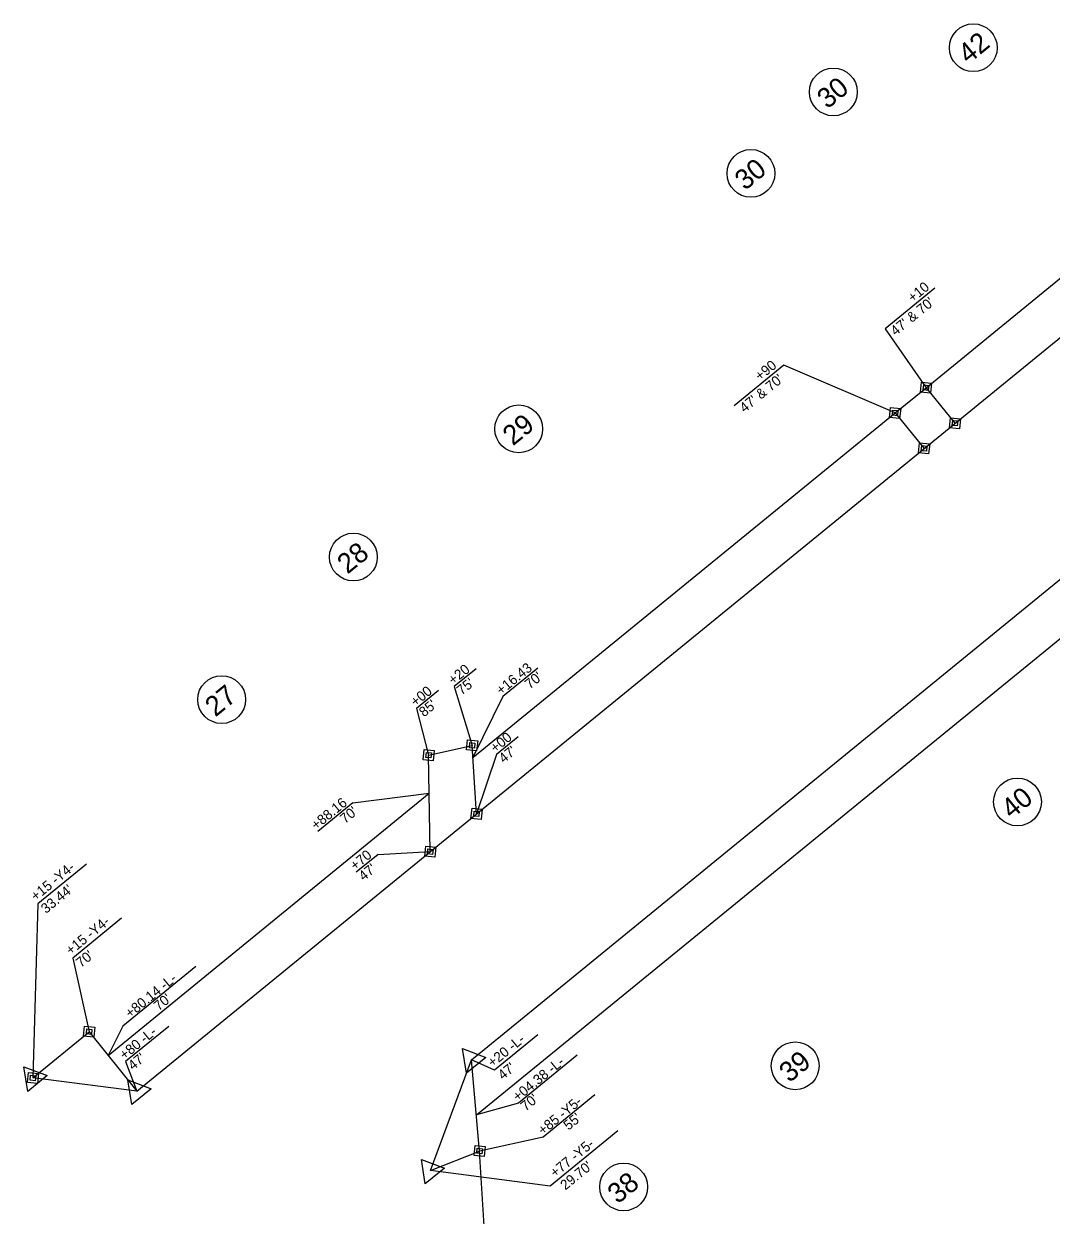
# Model space of a CAD drawing. Extents: x 2320946 to 2332748, y 597838 to 612698.
# Drawn here: x 2322965 to 2323481, y 599108 to 599706 of the extents above; entities that cross this region are included whole.
import ezdxf

# ---------------------------------------------------------------- set-up
doc = ezdxf.new("R2010")
doc.units = 0
for name, color, linetype in [('Prop Easement Construction', 7, 'Continuous'), ('Prop Easement Construction Station Offsets', 7, 'Continuous'), ('Prop Easement Permanent Drainage', 7, 'Continuous'), ('Prop Easement Permanent Drainage Station Offsets', 7, 'Continuous'), ('Prop Easement Permanent Utility', 7, 'Continuous'), ('Prop Easement Permanent Utility Station Offsets', 7, 'Continuous'), ('Prop Parcel Number CELL', 7, 'Continuous'), ('Prop ROW Marker CELL', 7, 'Continuous'), ('Prop ROW Permanent Easement CELL', 7, 'Continuous'), ('Prop ROW RW Lines', 7, 'Continuous'), ('Prop ROW Station Offsets', 7, 'Continuous')]:
    doc.layers.add(name, color=color, linetype=linetype)

msp = doc.modelspace()

# ---------------------------------------------------------------- linework, layer by layer
at = {"layer": 'Prop Easement Construction'}
for p, q in [((2323417.87, 599523.08), (2323545.68, 599627.42)), ((2323190.45, 599337.42), (2323402.37, 599510.43)), ((2323192.2, 599158.11), (2323576.17, 599471.58)), ((2323007.42, 599187.99), (2323168.55, 599319.54)), ((2323196.52, 599097.06), (2323193.8, 599139.98))]:
    msp.add_line(p, q, dxfattribs=at)
at = {"layer": 'Prop Easement Construction Station Offsets'}
for p, q in [((2323222.96, 599382.4), (2323205.43, 599368.09)), ((2323130.23, 599314.81), (2323112.61, 599300.42)), ((2323051.43, 599232.54), (2323014.7, 599202.56)), ((2323242.75, 599188.04), (2323213.38, 599164.06))]:
    msp.add_line(p, q, dxfattribs=at)
for points in [[(2323205.43, 599368.09), (2323190.45, 599337.42)], [(2323130.23, 599314.81), (2323168.55, 599319.54)], [(2323014.7, 599202.56), (2323007.42, 599187.99)], [(2323213.41, 599164.03), (2323192.2, 599158.11)]]:
    msp.add_lwpolyline(points, dxfattribs=at)
at = {"layer": 'Prop Easement Permanent Drainage'}
for p, q in [((2323402.37, 599510.43), (2323417.87, 599523.08)), ((2323417.87, 599523.08), (2323432.41, 599505.26)), ((2323402.37, 599510.43), (2323416.92, 599492.61))]:
    msp.add_line(p, q, dxfattribs=at)
at = {"layer": 'Prop Easement Permanent Drainage Station Offsets'}
for p, q in [((2323422.28, 599573.04), (2323397.29, 599552.64)), ((2323346.51, 599534.47), (2323321.52, 599514.07)), ((2323402.37, 599510.43), (2323346.51, 599534.47))]:
    msp.add_line(p, q, dxfattribs=at)
msp.add_lwpolyline([(2323397.29, 599552.64), (2323417.87, 599523.08)], dxfattribs=at)
at = {"layer": 'Prop Easement Permanent Utility'}
for p, q in [((2323168.24, 599338.65), (2323190.06, 599343.55)), ((2323192.27, 599309.21), (2323190.06, 599343.55)), ((2323169.03, 599290.24), (2323168.24, 599338.65)), ((2322969.61, 599176.64), (2322997.84, 599199.87)), ((2322997.84, 599199.87), (2323021.85, 599170.08)), ((2323193.8, 599139.98), (2323189.75, 599185.81)), ((2323169.13, 599130.2), (2323193.8, 599139.98))]:
    msp.add_line(p, q, dxfattribs=at)
at = {"layer": 'Prop Easement Permanent Utility Station Offsets'}
for p, q in [((2323192.1, 599382), (2323181.13, 599373.04)), ((2323173.17, 599371.05), (2323162.2, 599362.1)), ((2323213.22, 599347.88), (2323202.25, 599338.93)), ((2323142.86, 599288.81), (2323131.89, 599279.85)), ((2323014.08, 599256.83), (2322989.61, 599236.85)), ((2323251.72, 599168.22), (2323225.7, 599146.97))]:
    msp.add_line(p, q, dxfattribs=at)
for points in [[(2323181.13, 599373.04), (2323190.06, 599343.55)], [(2323162.2, 599362.1), (2323168.24, 599338.65)], [(2323202.25, 599338.93), (2323192.27, 599309.21)], [(2323142.86, 599288.81), (2323169.03, 599290.24)], [(2322989.61, 599236.85), (2322997.84, 599199.87)], [(2323225.7, 599146.97), (2323193.8, 599139.98)]]:
    msp.add_lwpolyline(points, dxfattribs=at)
at = {"layer": 'Prop Parcel Number CELL'}
for p, q in [((2323441.61, 599693.73), (2323441.61, 599693.73)), ((2323371.35, 599671.55), (2323371.35, 599671.55)), ((2323330, 599630.66), (2323330, 599630.66)), ((2323213.45, 599502.42), (2323213.45, 599502.42)), ((2323130.47, 599438.09), (2323130.47, 599438.09)), ((2323064.34, 599366.54), (2323064.34, 599366.54)), ((2323463.77, 599315.17), (2323463.77, 599315.17)), ((2323352.22, 599182.76), (2323352.22, 599182.76)), ((2323266.13, 599121.95), (2323266.13, 599121.95))]:
    msp.add_line(p, q, dxfattribs=at)
for centre in [(2323441.61, 599693.73), (2323371.35, 599671.55), (2323330, 599630.66), (2323213.45, 599502.42), (2323130.47, 599438.09), (2323064.34, 599366.54), (2323463.77, 599315.17), (2323352.22, 599182.76), (2323266.13, 599121.95)]:
    msp.add_circle(centre, 12, dxfattribs=at)
at = {"layer": 'Prop ROW Marker CELL'}
for p, q in [((2323417.87, 599523.08), (2323417.87, 599523.08)), ((2323402.37, 599510.43), (2323402.37, 599510.43)), ((2323432.41, 599505.26), (2323432.41, 599505.26)), ((2323416.92, 599492.61), (2323416.92, 599492.61)), ((2323190.06, 599343.55), (2323190.06, 599343.55)), ((2323168.24, 599338.65), (2323168.24, 599338.65)), ((2323192.27, 599309.21), (2323192.27, 599309.21)), ((2323169.03, 599290.24), (2323169.03, 599290.24)), ((2322997.84, 599199.87), (2322997.84, 599199.87)), ((2323189.75, 599185.81), (2323189.75, 599185.81)), ((2322969.61, 599176.64), (2322969.61, 599176.64)), ((2322969.61, 599176.64), (2322969.61, 599176.64)), ((2323021.85, 599170.08), (2323021.85, 599170.08)), ((2323193.8, 599139.98), (2323193.8, 599139.98)), ((2323169.13, 599130.2), (2323169.13, 599130.2))]:
    msp.add_line(p, q, dxfattribs=at)
for points in [[(2323187.18, 599179.06), (2323185.2, 599191.38), (2323196.87, 599186.97)], [(2322967.04, 599169.9), (2322965.05, 599182.22), (2322976.72, 599177.81)], [(2323019.29, 599163.34), (2323017.3, 599175.66), (2323028.97, 599171.25)], [(2323166.56, 599123.46), (2323164.57, 599135.78), (2323176.24, 599131.36)]]:
    msp.add_lwpolyline(points, close=True, dxfattribs=at)
at = {"layer": 'Prop ROW Permanent Easement CELL'}
for points in [[(2323415.59, 599525.87), (2323420.65, 599525.35), (2323420.14, 599520.29), (2323415.08, 599520.8)], [(2323416.73, 599524.47), (2323419.26, 599524.22), (2323419, 599521.68), (2323416.47, 599521.94)], [(2323400.1, 599513.22), (2323405.16, 599512.71), (2323404.65, 599507.64), (2323399.58, 599508.15)], [(2323401.23, 599511.82), (2323403.77, 599511.57), (2323403.51, 599509.04), (2323400.98, 599509.29)], [(2323430.13, 599508.05), (2323435.2, 599507.54), (2323434.69, 599502.47), (2323429.62, 599502.98)], [(2323431.27, 599506.66), (2323433.8, 599506.4), (2323433.55, 599503.87), (2323431.02, 599504.12)], [(2323414.64, 599495.4), (2323419.71, 599494.89), (2323419.19, 599489.82), (2323414.13, 599490.34)], [(2323415.78, 599494.01), (2323418.31, 599493.75), (2323418.06, 599491.22), (2323415.52, 599491.47)], [(2323187.78, 599346.34), (2323192.85, 599345.83), (2323192.33, 599340.76), (2323187.27, 599341.28)], [(2323188.92, 599344.95), (2323191.45, 599344.69), (2323191.2, 599342.16), (2323188.66, 599342.41)], [(2323165.97, 599341.44), (2323171.03, 599340.93), (2323170.52, 599335.86), (2323165.45, 599336.37)], [(2323167.1, 599340.04), (2323169.64, 599339.79), (2323169.38, 599337.26), (2323166.85, 599337.51)], [(2323190, 599312), (2323195.06, 599311.49), (2323194.55, 599306.43), (2323189.49, 599306.94)], [(2323191.14, 599310.61), (2323193.67, 599310.35), (2323193.41, 599307.82), (2323190.88, 599308.08)], [(2323166.76, 599293.03), (2323171.82, 599292.52), (2323171.31, 599287.45), (2323166.25, 599287.97)], [(2323167.9, 599291.64), (2323170.43, 599291.38), (2323170.17, 599288.85), (2323167.64, 599289.1)], [(2322995.56, 599202.65), (2323000.63, 599202.14), (2323000.11, 599197.08), (2322995.05, 599197.59)], [(2322996.7, 599201.26), (2322999.23, 599201), (2322998.98, 599198.47), (2322996.44, 599198.73)], [(2322967.33, 599179.43), (2322972.39, 599178.92), (2322971.88, 599173.85), (2322966.82, 599174.37)], [(2322968.47, 599178.04), (2322971, 599177.78), (2322970.74, 599175.25), (2322968.21, 599175.5)], [(2323191.52, 599142.77), (2323196.59, 599142.26), (2323196.07, 599137.19), (2323191.01, 599137.7)], [(2323192.66, 599141.37), (2323195.19, 599141.12), (2323194.93, 599138.59), (2323192.4, 599138.84)]]:
    msp.add_lwpolyline(points, close=True, dxfattribs=at)
at = {"layer": 'Prop ROW RW Lines'}
for p, q in [((2323021.85, 599170.08), (2323653.18, 599685.5)), ((2323189.75, 599185.81), (2323538.33, 599470.39)), ((2323169.13, 599130.2), (2323189.75, 599185.81)), ((2323021.85, 599170.08), (2322969.61, 599176.64))]:
    msp.add_line(p, q, dxfattribs=at)
at = {"layer": 'Prop ROW Station Offsets'}
for p, q in [((2322996.49, 599283.96), (2322972.01, 599263.98)), ((2322972.01, 599263.98), (2322969.61, 599176.64)), ((2323037.84, 599202.55), (2323016.12, 599184.82)), ((2323223.06, 599198.23), (2323201.34, 599180.51)), ((2323263.19, 599150.08), (2323229.22, 599122.35)), ((2323229.22, 599122.35), (2323169.13, 599130.2))]:
    msp.add_line(p, q, dxfattribs=at)
for points in [[(2323016.12, 599184.82), (2323021.85, 599170.08)], [(2323201.34, 599180.51), (2323189.75, 599185.81)]]:
    msp.add_lwpolyline(points, dxfattribs=at)

# ---------------------------------------------------------------- texts
at = {"layer": 'Prop Easement Construction Station Offsets'}
for s, p in [('+16.43', (2323204.65, 599368.58)), ("70'", (2323219.02, 599371.59)), ('+88.16', (2323111.78, 599300.87)), ("70'", (2323126.29, 599304.01)), ('+80.14 -L-', (2323018.45, 599206.43)), ("70'", (2323032.79, 599210.07)), ('+04.38 -L-', (2323212.98, 599164.55)), ("70'", (2323216.94, 599159.71))]:
    msp.add_text(s, height=5, rotation=39.22799, dxfattribs=at).set_placement(p)
at = {"layer": 'Prop Easement Permanent Drainage Station Offsets'}
for s, p in [('+10', (2323411.22, 599565.63)), ("47' & 70'", (2323402.58, 599548.89)), ('+90', (2323334.53, 599526.3)), ("47' & 70'", (2323326.81, 599510.32))]:
    msp.add_text(s, height=5, rotation=39.22799, dxfattribs=at).set_placement(p)
at = {"layer": 'Prop Easement Permanent Utility Station Offsets'}
for s, p in [('+20', (2323180.58, 599373.72)), ('+00', (2323161.65, 599362.77)), ("75'", (2323184.85, 599368.49)), ("85'", (2323165.92, 599357.55)), ('+00', (2323201.69, 599339.61)), ("47'", (2323205.96, 599334.38)), ('+70', (2323131.34, 599280.53)), ("47'", (2323135.61, 599275.3)), ('+15 -Y4-', (2322988.62, 599238.06)), ("70'", (2322993.76, 599231.77)), ('+85 -Y5-', (2323225.61, 599147.71)), ("55'", (2323238.44, 599150.11))]:
    msp.add_text(s, height=5, rotation=39.22799, dxfattribs=at).set_placement(p)
at = {"layer": 'Prop Parcel Number CELL'}
for s, p in [('42', (2323439.14, 599685.25)), ('30', (2323368.38, 599662.67)), ('30', (2323327.04, 599621.79)), ('29', (2323210.55, 599493.6)), ('28', (2323127.51, 599429.22)), ('27', (2323061.2, 599357.53)), ('40', (2323460.8, 599306.29)), ('39', (2323349.32, 599173.94)), ('38', (2323263.17, 599113.08))]:
    msp.add_text(s, height=10, rotation=39.22799, dxfattribs=at).set_placement(p)
at = {"layer": 'Prop ROW Station Offsets'}
for s, p in [('+15 -Y4-', (2322971.03, 599265.19)), ("33.44'", (2322976.17, 599258.9)), ('+80 -L-', (2323015.57, 599185.5)), ('+20 -L-', (2323200.36, 599181.72)), ("47'", (2323019.84, 599180.27)), ("47'", (2323205.49, 599175.42)), ('+77 -Y5-', (2323231.72, 599126.41)), ("29.70'", (2323236.86, 599120.11))]:
    msp.add_text(s, height=5, rotation=39.22799, dxfattribs=at).set_placement(p)

doc.saveas('drawing.dxf')
